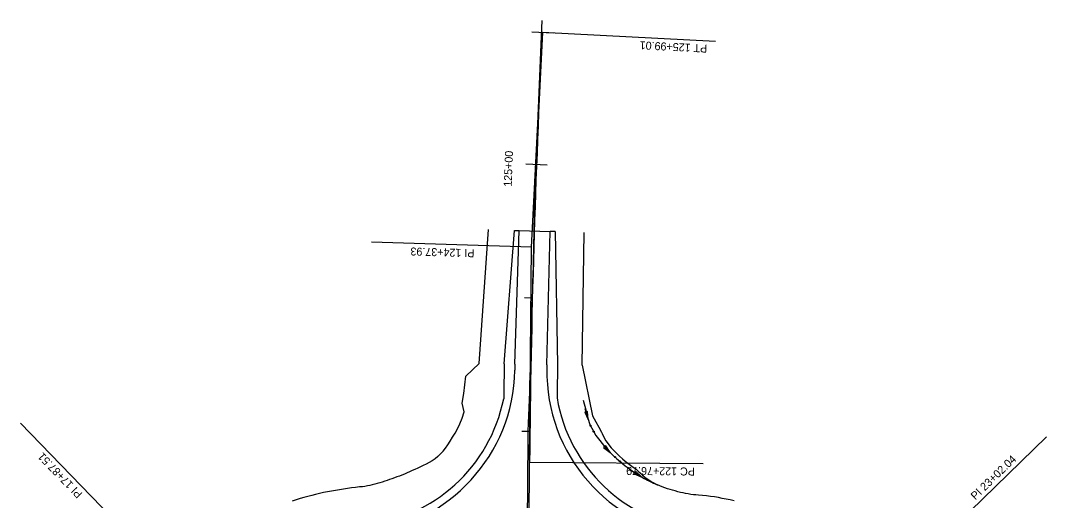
# Model space of a CAD drawing. Extents: x 1311167 to 1314552, y 2087587 to 2090602.
# Drawn here: x 1313625 to 1314395, y 2090242 to 2090602 of the extents above; entities that cross this region are included whole.
import ezdxf

# ---------------------------------------------------------------- set-up
doc = ezdxf.new("R2010")
doc.units = 0
for name, color, linetype in [('R_Bridge', 7, 'Continuous'), ('R_Guardrail', 7, 'Continuous'), ('R_Horz Alg Stationing', 7, 'Continuous'), ('R_Proposed Road', 7, 'Continuous'), ('R_Shld_GR', 7, 'Continuous'), ('S_DITCHLINE', 7, 'Continuous'), ('S_EDGE_CONCRETE', 7, 'Continuous'), ('S_EDGE_PAVEMENT', 7, 'Continuous'), ('S_PAVEMENT_CROWN', 7, 'Continuous')]:
    doc.layers.add(name, color=color, linetype=linetype)

msp = doc.modelspace()

# ---------------------------------------------------------------- linework, layer by layer
at = {"layer": 'R_Bridge'}
for points in [[(1314008.61, 2090593.72), (1314024.59, 2090592.9)], [(1314008.61, 2090593.72), (1314024.59, 2090592.9)], [(1314004.21, 2090494.7), (1314020.19, 2090494.09)], [(1314003.06, 2090394.59), (1314009.06, 2090394.44)], [(1314001.23, 2090294.53), (1314007.23, 2090294.46)]]:
    msp.add_lwpolyline(points, dxfattribs=at)
at = {"layer": 'R_Guardrail'}
for points in [[(1314006.99, 2090271.25), (1314008.4, 2090432.38), (1314016.6, 2090593.31)], [(1314016.6, 2090593.31), (1314146.43, 2090586.69)], [(1314008.4, 2090432.38), (1313888.45, 2090435.96)], [(1314006.99, 2090271.25), (1314136.99, 2090270.12)]]:
    msp.add_lwpolyline(points, dxfattribs=at)
at = {"layer": 'R_Horz Alg Stationing'}
for p, q in [((1314011.09, 2090476.71), (1314016.38, 2090602.09)), ((1313999.49, 2089462.84), (1314005.79, 2090288.55))]:
    msp.add_line(p, q, dxfattribs=at)
msp.add_arc((1302555.38, 2090705.37), 11458, 357.915213, 358.856479, dxfattribs=at)
at = {"layer": 'R_Proposed Road'}
for p in [(1314005.29, 2090076.56), (1314005.33, 2090080.47), (1314005.33, 2090080.47)]:
    msp.add_line(p, (1314006.99, 2090271.25), dxfattribs=at)
msp.add_arc((1321646.14, 2090204.59), 7639.44, 177.083333, 179.5, dxfattribs=at)
msp.add_arc((1321646.14, 2090204.59), 7639.44, 177.083333, 179.5, dxfattribs=at)
msp.add_arc((1321646.14, 2090204.59), 7639.44, 177.083333, 179.5, dxfattribs=at)
at = {"layer": 'R_Shld_GR'}
for points in [[(1313708.76, 2090214.29), (1313625.25, 2090300.46)], [(1314308.48, 2090206.44), (1314394.53, 2090290.07)]]:
    msp.add_lwpolyline(points, dxfattribs=at)
at = {"layer": 'S_DITCHLINE'}
for p, q in [((1314050.4, 2090309.27), (1314048.36, 2090308.73)), ((1314048.36, 2090308.73), (1314050.89, 2090303.19)), ((1314050.89, 2090303.19), (1314050.4, 2090309.27)), ((1314064.04, 2090283.55), (1314062.49, 2090282.12)), ((1314062.49, 2090282.12), (1314067.34, 2090278.43)), ((1314067.34, 2090278.43), (1314064.04, 2090283.55)), ((1314086.5, 2090264.15), (1314085.38, 2090262.36)), ((1314085.38, 2090262.36), (1314091.02, 2090260.07)), ((1314091.02, 2090260.07), (1314086.5, 2090264.15))]:
    msp.add_line(p, q, dxfattribs=at)
for points in [[(1314047.19, 2090317.73), (1314049.03, 2090310.36), (1314050.63, 2090304.19), (1314052.21, 2090299.32), (1314056.54, 2090291.08), (1314063.48, 2090282.6), (1314065.76, 2090280.14), (1314068, 2090277.86), (1314070.2, 2090275.73), (1314072.37, 2090273.74), (1314074.51, 2090271.87), (1314076.62, 2090270.11), (1314078.71, 2090268.44), (1314080.78, 2090266.88), (1314082.84, 2090265.39), (1314084.87, 2090263.99), (1314086.89, 2090262.66), (1314088.9, 2090261.4), (1314090.9, 2090260.21), (1314092.88, 2090259.08), (1314094.85, 2090258.01), (1314096.82, 2090257), (1314098.77, 2090256.04), (1314100.72, 2090255.13), (1314102.63, 2090254.21)], [(1314047.19, 2090317.73), (1314049.03, 2090310.36), (1314050.63, 2090304.19), (1314050.95, 2090303.21)], [(1314048.41, 2090311.51), (1314050.27, 2090305.46)], [(1314057.56, 2090289.84), (1314057.58, 2090289.81)], [(1314057.58, 2090289.81), (1314063.48, 2090282.6), (1314065.76, 2090280.14), (1314067.39, 2090278.48)], [(1314078.6, 2090268.53), (1314078.63, 2090268.51)], [(1314078.63, 2090268.51), (1314078.71, 2090268.44), (1314080.78, 2090266.88), (1314082.84, 2090265.39), (1314084.87, 2090263.99), (1314086.89, 2090262.66), (1314088.9, 2090261.4), (1314090.9, 2090260.21), (1314091.05, 2090260.12)]]:
    msp.add_lwpolyline(points, dxfattribs=at)
for centre in [(1314052.67, 2090298.53), (1314055, 2090294.09), (1314071.02, 2090275.03), (1314074.76, 2090271.7), (1314095.46, 2090257.74), (1314099.95, 2090255.53)]:
    msp.add_circle(centre, 0.375, dxfattribs=at)
at = {"layer": 'S_EDGE_CONCRETE'}
for p, q in [((1313969.23, 2090345.16), (1313976.22, 2090445.5)), ((1314046.26, 2090343.75), (1314047.79, 2090443.25))]:
    msp.add_line(p, q, dxfattribs=at)
for points in [[(1313942.1, 2090279.45), (1313943.93, 2090281.78), (1313945.75, 2090284.27), (1313947.49, 2090286.98), (1313949.22, 2090289.88), (1313951.12, 2090292.89), (1313952.98, 2090296.2), (1313954.78, 2090299.88), (1313956.42, 2090304.07), (1313957.81, 2090308.93), (1313956.45, 2090315.51), (1313957.55, 2090322.68), (1313959.15, 2090335.64), (1313969.23, 2090345.16)], [(1314046.26, 2090343.75), (1314054.24, 2090305.79), (1314056.64, 2090301.31), (1314058.76, 2090297.34), (1314060.81, 2090293.79), (1314061.43, 2090292.78), (1314062.5, 2090290.38), (1314064.09, 2090287.15)], [(1314064.09, 2090287.15), (1314068.17, 2090281.94), (1314070.3, 2090279.69), (1314072.39, 2090277.59), (1314074.46, 2090275.63), (1314076.51, 2090273.78), (1314078.53, 2090272.04), (1314080.54, 2090270.39), (1314082.53, 2090268.84), (1314084.54, 2090267.42), (1314086.54, 2090266.08), (1314088.28, 2090264.49), (1314090, 2090262.93), (1314091.74, 2090261.44), (1314093.48, 2090260.01), (1314095.24, 2090258.64), (1314097.03, 2090257.37), (1314098.84, 2090256.16), (1314102.77, 2090254.15)], [(1313942.1, 2090279.45), (1313940.12, 2090277.37), (1313938.13, 2090275.45), (1313936.16, 2090273.63), (1313933.88, 2090272.26), (1313931.62, 2090271), (1313929.41, 2090269.82), (1313927.25, 2090268.71), (1313925.13, 2090267.66), (1313923.04, 2090266.67), (1313920.99, 2090265.72), (1313918.97, 2090264.83), (1313916.99, 2090263.96), (1313915.05, 2090263.11), (1313913.13, 2090262.3), (1313911.22, 2090261.53), (1313909.34, 2090260.79), (1313907.46, 2090260.1), (1313905.6, 2090259.44), (1313903.75, 2090258.83), (1313901.91, 2090258.25), (1313900.11, 2090257.58), (1313898.34, 2090256.9), (1313896.47, 2090256.24), (1313894.6, 2090255.64), (1313892.74, 2090255.09), (1313890.89, 2090254.59), (1313889.03, 2090254.14), (1313887.18, 2090253.73), (1313885.34, 2090253.37), (1313883.48, 2090253.07), (1313881.63, 2090252.82), (1313879.36, 2090252.59), (1313876.35, 2090252.24), (1313873.35, 2090251.86), (1313870.35, 2090251.43), (1313867.36, 2090250.99), (1313864.37, 2090250.49), (1313861.39, 2090249.97), (1313858.4, 2090249.48), (1313855.42, 2090248.95), (1313852.45, 2090248.35), (1313849.49, 2090247.7), (1313846.53, 2090247.03), (1313843.58, 2090246.32), (1313840.64, 2090245.57), (1313837.72, 2090244.75), (1313834.82, 2090243.87), (1313831.93, 2090242.96), (1313829.04, 2090242.03)], [(1314160.25, 2090242.26), (1314157.33, 2090242.9), (1314154.39, 2090243.5), (1314151.46, 2090244.08), (1314148.52, 2090244.67), (1314145.57, 2090245.15), (1314142.61, 2090245.58), (1314139.64, 2090245.96), (1314136.66, 2090246.22), (1314133.68, 2090246.48), (1314131.7, 2090246.62), (1314129.76, 2090246.81), (1314127.82, 2090247.05), (1314125.88, 2090247.35), (1314123.94, 2090247.7), (1314121.99, 2090248.1), (1314120.03, 2090248.56), (1314118.06, 2090249.07), (1314116.08, 2090249.6), (1314114.17, 2090250.11), (1314112.26, 2090250.67), (1314110.34, 2090251.28), (1314108.42, 2090251.94), (1314106.49, 2090252.64), (1314104.56, 2090253.4), (1314102.77, 2090254.15)]]:
    msp.add_lwpolyline(points, dxfattribs=at)
at = {"layer": 'S_EDGE_PAVEMENT'}
for p, q in [((1313987.98, 2090344.82), (1313995.69, 2090444.89)), ((1313995.69, 2090444.89), (1313999.25, 2090444.78)), ((1314026.2, 2090443.93), (1314022.48, 2090444.05)), ((1314026.2, 2090443.93), (1314027.98, 2090344.09))]:
    msp.add_line(p, q, dxfattribs=at)
for centre, radius, start, end in [((1321646.14, 2090204.59), 7659.44, 178.950936, 179.146389), ((1321646.14, 2090204.59), 7619.44, 178.950936, 179.137193), ((1313870.92, 2090342.33), 119, 276.05442, 348.54608), ((1314144.91, 2090339.12), 119, 189.57455, 263.01434)]:
    msp.add_arc(centre, radius, start, end, dxfattribs=at)
at = {"layer": 'S_PAVEMENT_CROWN'}
for p, q in [((1313995.98, 2090344.67), (1313999.25, 2090444.78)), ((1313999.25, 2090444.78), (1314022.48, 2090444.05)), ((1314019.98, 2090344.24), (1314022.48, 2090444.05))]:
    msp.add_line(p, q, dxfattribs=at)
for centre, radius, start, end in [((1313870.92, 2090342.33), 125, 276.05442, 358.9851), ((1321646.14, 2090204.59), 7651.44, 178.950936, 178.9851), ((1314144.91, 2090339.12), 125, 178.97255, 263.01434), ((1321646.14, 2090204.59), 7627.44, 178.950936, 178.972554)]:
    msp.add_arc(centre, radius, start, end, dxfattribs=at)

# ---------------------------------------------------------------- texts
at = {"layer": 'R_Bridge'}
msp.add_text('125+00', height=6, rotation=87.82594, dxfattribs=at).set_placement((1313993.54, 2090477.44))
at = {"layer": 'R_Guardrail'}
for s, rotation, p in [('PT 125+99.01', 177.08333, (1314140.28, 2090584)), ('PI 124+37.93', 178.29167, (1313965.7, 2090430.65)), ('PC 122+76.79', 179.5, (1314130.96, 2090267.17))]:
    msp.add_text(s, height=6, rotation=rotation, dxfattribs=at).set_placement(p)
at = {"layer": 'R_Shld_GR'}
for s, rotation, p in [('PI 17+87.51', 134.1, (1313672.16, 2090247.75)), ('PI 23+02.04', 44.18125, (1314341.26, 2090242.48))]:
    msp.add_text(s, height=6, rotation=rotation, dxfattribs=at).set_placement(p)

doc.saveas('drawing.dxf')
